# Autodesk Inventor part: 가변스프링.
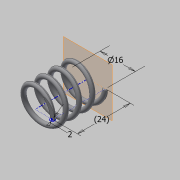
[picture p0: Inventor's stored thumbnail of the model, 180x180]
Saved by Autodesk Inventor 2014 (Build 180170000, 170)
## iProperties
Created: 2015-04
Part Number: 가변스프링.
Material: Generic
Document SubType Name: Modeling
Designer: Administrator
Density: 1 g/cm^3
Appearance: Default
Author: Administrator
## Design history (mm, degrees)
sketch "스케치1"
  geometry: L1 (0, 0)-(8, 0); L2 (8, 0)-(8, 24); L3 (8, 24)-(0, 24); L4 (0, 24)-(0, 0); C1 r 1 at (8, 0)
  constraints: 8 end point, 2 parallel, 1 centre point, 1 coincident, 1 horizontal, 1 perpendicular
  dimensions: "d0" = 16 diameter of L2 L4; "d1" = 24 distance between parallel lines of L1 L3 (derived); "d2" = 2 diameter of C1
feature "코일1" pitch "d3" = 10; turns "d5" = 4; dims "d4" = 24 (= d1), "d6" = 0, angle "d7" = 90 deg, angle "d8" = 90 deg, "d9" = 0, "d10" = 0
sketch "스케치2"
  geometry: L1 (-7, 0)-(-9, 0) reference; 1 further point
  constraints: 1 horizontal alignment
extrude "돌출1" cut sketch "스케치2" stored distance "d11" = 10; taper "d12" = 0 deg
node "작업 평면1"
sketch "스케치3"
  geometry: L1 (7, 0)-(9, 0) reference; 1 further point
  constraints: 1 horizontal alignment
extrude "돌출2" cut sketch "스케치3" stored distance "d13" = 10; taper "d14" = 0 deg
node "솔리드1"
node "절단 모서리 투영1"
node "절단 모서리 투영2"
